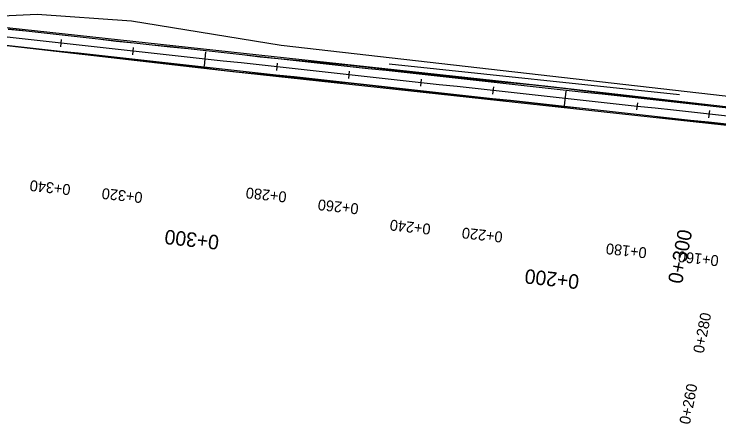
# Model space of a CAD drawing. Extents: x -636600 to -628587, y -1090963 to -1085869.
# Drawn here: x -635672.5 to -635477.9, y -1089253.6 to -1089140.3 of the extents above; entities that cross this region are included whole.
import ezdxf

# ---------------------------------------------------------------- set-up
doc = ezdxf.new("R2010")
doc.units = 0
for name, color, linetype in [('01_PARCELY_NÁVRH_PC', 7, 'Continuous'), ('06_ÚSES_IP_NAVRH', 7, 'Continuous'), ('HEKTOMETRY100', 7, 'Continuous'), ('HEKTOMETRY20', 7, 'Continuous'), ('situace_osa', 7, 'Continuous'), ('situace_těleso', 7, 'Continuous'), ('situace_vozovka', 7, 'Continuous')]:
    doc.layers.add(name, color=color, linetype=linetype)

msp = doc.modelspace()

# ---------------------------------------------------------------- linework, layer by layer
at = {"layer": '01_PARCELY_NÁVRH_PC'}
msp.add_lwpolyline([(-635697.5, -1089141.66), (-635695.21, -1089141.78), (-635666.07, -1089140.35), (-635640.03, -1089142.17), (-635598.78, -1089148.91), (-635435.9, -1089167.57), (-635442.29, -1089169.87), (-635524.26, -1089160.45)], close=True, dxfattribs=at)
msp.add_lwpolyline([(-635678.5, -1089148.61), (-635612.92, -1089156.15), (-635443.56, -1089174.51), (-635439.94, -1089176.47), (-635437.4, -1089179.68), (-635436.33, -1089183.55), (-635432.84, -1089163.39), (-635435.9, -1089167.57), (-635442.29, -1089169.87), (-635524.26, -1089160.45), (-635697.5, -1089141.66)], dxfattribs=at)
at = {"layer": '06_ÚSES_IP_NAVRH'}
msp.add_line((-635568.9, -1089154.1), (-635488.83, -1089162.59), dxfattribs=at)
at = {"layer": 'HEKTOMETRY100'}
for points in [[(-635619.93, -1089154.75), (-635619.49, -1089150.77)], [(-635520.53, -1089165.65), (-635520.09, -1089161.67)]]:
    msp.add_lwpolyline(points, dxfattribs=at)
at = {"layer": 'HEKTOMETRY20'}
for points in [[(-635659.58, -1089149.4), (-635659.36, -1089147.41)], [(-635639.7, -1089151.58), (-635639.48, -1089149.59)], [(-635599.94, -1089155.94), (-635599.72, -1089153.95)], [(-635580.06, -1089158.12), (-635579.84, -1089156.13)], [(-635560.18, -1089160.29), (-635559.96, -1089158.31)], [(-635540.3, -1089162.47), (-635540.08, -1089160.49)], [(-635500.54, -1089166.83), (-635500.32, -1089164.84)], [(-635480.65, -1089169.01), (-635480.44, -1089167.02)]]:
    msp.add_lwpolyline(points, dxfattribs=at)
at = {"layer": 'situace_osa'}
msp.add_lwpolyline([(-635475.58, -1089168.56), (-635480.55, -1089168.02), (-635485.52, -1089167.47), (-635490.49, -1089166.93), (-635495.46, -1089166.38), (-635500.43, -1089165.84), (-635505.4, -1089165.29), (-635510.37, -1089164.75), (-635515.34, -1089164.2), (-635520.31, -1089163.66), (-635525.28, -1089163.11), (-635530.25, -1089162.57), (-635535.22, -1089162.02), (-635540.19, -1089161.48), (-635545.16, -1089160.94), (-635550.13, -1089160.39), (-635555.1, -1089159.85), (-635560.07, -1089159.3), (-635565.04, -1089158.76), (-635570.01, -1089158.21), (-635574.98, -1089157.67), (-635579.95, -1089157.12), (-635584.92, -1089156.58), (-635589.89, -1089156.03), (-635594.86, -1089155.49), (-635599.83, -1089154.94), (-635604.8, -1089154.4), (-635609.77, -1089153.85), (-635614.74, -1089153.31), (-635619.71, -1089152.76), (-635624.68, -1089152.22), (-635629.65, -1089151.67), (-635634.62, -1089151.13), (-635639.59, -1089150.58), (-635644.56, -1089150.04), (-635649.53, -1089149.49), (-635654.5, -1089148.95), (-635659.47, -1089148.4), (-635664.44, -1089147.86), (-635669.41, -1089147.31), (-635674.38, -1089146.77)], dxfattribs=at)
at = {"layer": 'situace_těleso'}
for points in [[(-635674.14, -1089144.51), (-635669.16, -1089145.01), (-635664.19, -1089145.51), (-635659.22, -1089146.05), (-635654.25, -1089146.63), (-635649.28, -1089147.22), (-635644.32, -1089147.8), (-635639.35, -1089148.32), (-635634.37, -1089148.85), (-635629.4, -1089149.37), (-635624.43, -1089149.89), (-635619.45, -1089150.41), (-635614.48, -1089150.95), (-635609.52, -1089151.55), (-635604.56, -1089152.16), (-635599.58, -1089152.63), (-635594.6, -1089153.09), (-635589.62, -1089153.54), (-635584.64, -1089154), (-635579.66, -1089154.46), (-635574.69, -1089154.99), (-635569.72, -1089155.54), (-635564.75, -1089156.1), (-635559.78, -1089156.66), (-635554.81, -1089157.22), (-635549.84, -1089157.78), (-635544.87, -1089158.34), (-635539.9, -1089158.87), (-635534.93, -1089159.36), (-635529.95, -1089159.84), (-635524.98, -1089160.39), (-635520.01, -1089160.95), (-635515.04, -1089161.51), (-635510.07, -1089162.09), (-635505.11, -1089162.69), (-635500.15, -1089163.29), (-635495.18, -1089163.88), (-635490.22, -1089164.48), (-635485.25, -1089165.08), (-635480.29, -1089165.67), (-635475.32, -1089166.27)], [(-635475.84, -1089170.97), (-635480.81, -1089170.39), (-635485.77, -1089169.82), (-635490.74, -1089169.24), (-635495.71, -1089168.66), (-635500.67, -1089168.1), (-635505.64, -1089167.55), (-635510.61, -1089167), (-635515.58, -1089166.45), (-635520.56, -1089165.93), (-635525.53, -1089165.4), (-635530.5, -1089164.86), (-635535.47, -1089164.34), (-635540.44, -1089163.81), (-635545.41, -1089163.26), (-635550.38, -1089162.72), (-635555.35, -1089162.18), (-635560.32, -1089161.63), (-635565.3, -1089161.09), (-635570.27, -1089160.55), (-635575.23, -1089159.97), (-635580.2, -1089159.44), (-635585.18, -1089158.96), (-635590.16, -1089158.46), (-635595.13, -1089157.96), (-635600.11, -1089157.47), (-635605.08, -1089156.97), (-635610.06, -1089156.46), (-635615.03, -1089155.91), (-635619.99, -1089155.32), (-635624.96, -1089154.72), (-635629.92, -1089154.13), (-635634.89, -1089153.54), (-635639.85, -1089152.94), (-635644.82, -1089152.35), (-635649.78, -1089151.76), (-635654.75, -1089151.2), (-635659.73, -1089150.7), (-635664.7, -1089150.19), (-635669.66, -1089149.57), (-635674.63, -1089149.03)]]:
    msp.add_lwpolyline(points, dxfattribs=at)
at = {"layer": 'situace_vozovka'}
for points in [[(-635475.33, -1089166.33), (-635480.3, -1089165.78), (-635485.27, -1089165.24), (-635490.24, -1089164.69), (-635495.21, -1089164.15), (-635500.18, -1089163.6), (-635505.15, -1089163.06), (-635510.12, -1089162.51), (-635515.09, -1089161.97), (-635520.06, -1089161.42), (-635525.03, -1089160.88), (-635530, -1089160.33), (-635534.97, -1089159.79), (-635539.94, -1089159.24), (-635544.91, -1089158.7), (-635549.88, -1089158.15), (-635554.85, -1089157.61), (-635559.82, -1089157.06), (-635564.79, -1089156.52), (-635569.76, -1089155.97), (-635574.73, -1089155.43), (-635579.7, -1089154.88), (-635584.68, -1089154.34), (-635589.65, -1089153.8), (-635594.62, -1089153.25), (-635599.59, -1089152.71), (-635604.56, -1089152.16), (-635609.53, -1089151.62), (-635614.5, -1089151.07), (-635619.47, -1089150.53), (-635624.44, -1089149.98), (-635629.41, -1089149.44), (-635634.38, -1089148.89), (-635639.35, -1089148.35), (-635644.32, -1089147.8), (-635649.29, -1089147.26), (-635654.26, -1089146.71), (-635659.23, -1089146.17), (-635664.2, -1089145.62), (-635669.17, -1089145.08), (-635674.14, -1089144.53)], [(-635475.82, -1089170.8), (-635480.79, -1089170.25), (-635485.76, -1089169.71), (-635490.73, -1089169.17), (-635495.7, -1089168.62), (-635500.67, -1089168.08), (-635505.64, -1089167.53), (-635510.61, -1089166.99), (-635515.58, -1089166.44), (-635520.55, -1089165.9), (-635525.52, -1089165.35), (-635530.49, -1089164.81), (-635535.46, -1089164.26), (-635540.43, -1089163.72), (-635545.4, -1089163.17), (-635550.37, -1089162.63), (-635555.34, -1089162.08), (-635560.31, -1089161.54), (-635565.28, -1089160.99), (-635570.25, -1089160.45), (-635575.22, -1089159.9), (-635580.2, -1089159.36), (-635585.17, -1089158.81), (-635590.14, -1089158.27), (-635595.11, -1089157.72), (-635600.08, -1089157.18), (-635605.05, -1089156.63), (-635610.02, -1089156.09), (-635614.99, -1089155.54), (-635619.96, -1089155), (-635624.93, -1089154.45), (-635629.9, -1089153.91), (-635634.87, -1089153.36), (-635639.84, -1089152.82), (-635644.81, -1089152.27), (-635649.78, -1089151.73), (-635654.75, -1089151.19), (-635659.72, -1089150.64), (-635664.69, -1089150.1), (-635669.66, -1089149.55), (-635674.63, -1089149.01)]]:
    msp.add_lwpolyline(points, dxfattribs=at)

# ---------------------------------------------------------------- texts
at = {"layer": 'HEKTOMETRY100'}
for s, rotation, p in [('0+300', 173.7441, (-635615.72, -1089201.49)), ('0+300', 79.019, (-635488.09, -1089215.06)), ('0+200', 173.7441, (-635516.32, -1089212.38))]:
    msp.add_text(s, height=4, rotation=rotation, dxfattribs=at).set_placement(p)
at = {"layer": 'HEKTOMETRY20'}
for s, rotation, p in [('0+340', 173.7441, (-635656.75, -1089187.43)), ('0+320', 173.7441, (-635636.87, -1089189.61)), ('0+280', 173.7441, (-635597.11, -1089189.44)), ('0+260', 173.7441, (-635577.23, -1089192.72)), ('0+240', 173.7441, (-635557.35, -1089198.33)), ('0+220', 173.7441, (-635537.47, -1089200.51)), ('0+180', 173.7441, (-635497.71, -1089204.87)), ('0+160', 173.7441, (-635477.83, -1089207.05)), ('0+280', 79.019, (-635482.13, -1089234.22)), ('0+260', 79.019, (-635485.94, -1089253.86))]:
    msp.add_text(s, height=3, rotation=rotation, dxfattribs=at).set_placement(p)

doc.saveas('drawing.dxf')
